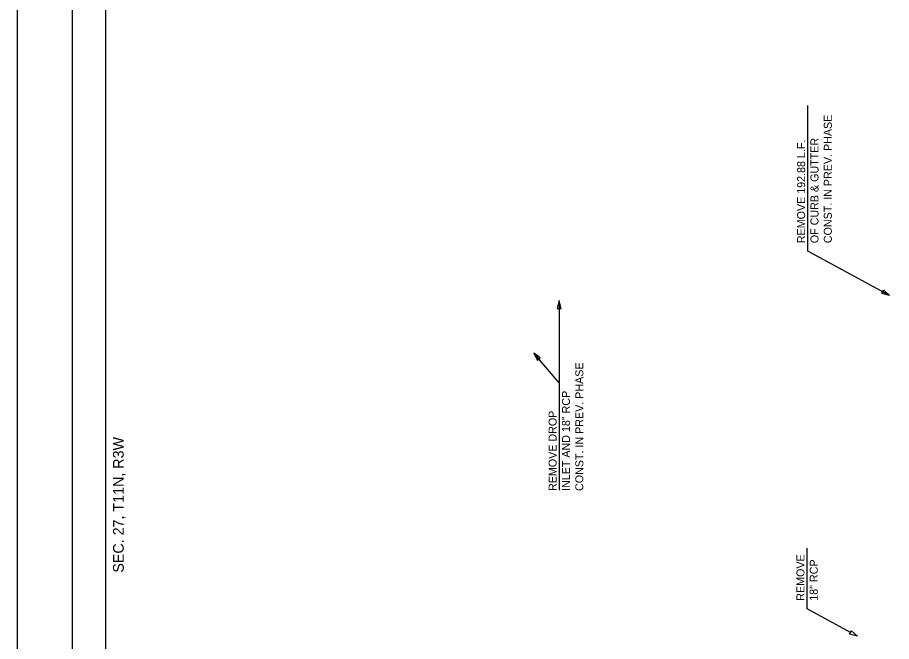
# Model space of a CAD drawing. Extents: x 2150259 to 2151459, y 143090 to 145092.
# Drawn here: x 2150259 to 2150914, y 144157 to 144624 of the extents above; entities that cross this region are included whole.
import ezdxf

# ---------------------------------------------------------------- set-up
doc = ezdxf.new("R2010")
doc.units = 0
for name, color, linetype in [('PR_Removal_Txt', 7, 'Continuous'), ('SHT_Plot_Shape_Full', 7, 'Continuous'), ('SHT_Plot_Shape_Half', 7, 'Continuous'), ('SHT_Sheet_Border', 7, 'Continuous'), ('SHT_Sheet_Txt', 7, 'Continuous')]:
    doc.layers.add(name, color=color, linetype=linetype)

msp = doc.modelspace()

# ---------------------------------------------------------------- linework, layer by layer
at = {"layer": 'PR_Removal_Txt'}
for p, q in [((2150851.5, 144455.26), (2150851.5, 144558.45)), ((2150665.27, 144350.64), (2150646.15, 144372.91)), ((2150665.27, 144344.64), (2150665.27, 144270.07)), ((2150850.96, 144187.3), (2150850.96, 144226.71))]:
    msp.add_line(p, q, dxfattribs=at)
for points in [[(2150912.82, 144416.01), (2150851.5, 144449.26), (2150851.5, 144455.26)], [(2150665.12, 144412.22), (2150665.27, 144350.64), (2150665.27, 144344.64)], [(2150883.51, 144163.57), (2150850.96, 144181.3), (2150850.96, 144187.3)]]:
    msp.add_lwpolyline(points, dxfattribs=at)
for points in [[(2150912.82, 144416.01), (2150907.01, 144417.5), (2150908.39, 144420.06)], [(2150665.12, 144412.22), (2150663.68, 144406.39), (2150666.59, 144406.4)], [(2150646.15, 144372.91), (2150648.83, 144367.55), (2150651.04, 144369.44)], [(2150888.63, 144160.79), (2150882.82, 144162.29), (2150884.21, 144164.85)]]:
    msp.add_lwpolyline(points, close=True, dxfattribs=at)
at = {"layer": 'SHT_Plot_Shape_Full'}
msp.add_lwpolyline([(2150259.22, 143292.05), (2150259.22, 145092.05), (2151459.22, 145092.05), (2151459.22, 143292.05)], close=True, dxfattribs=at)
at = {"layer": 'SHT_Plot_Shape_Half'}
msp.add_lwpolyline([(2150300.47, 143373.92), (2150300.47, 145073.92), (2151400.47, 145073.92), (2151400.47, 143373.92)], close=True, dxfattribs=at)
at = {"layer": 'SHT_Sheet_Border'}
msp.add_lwpolyline([(2151375.47, 145046.42), (2151375.47, 143471.42), (2150325.47, 143471.42), (2150325.47, 145046.42)], close=True, dxfattribs=at)

# ---------------------------------------------------------------- texts
at = {"layer": 'PR_Removal_Txt'}
for s, p in [('CONST. IN PREV. PHASE', (2150869.5, 144455.26)), ('REMOVE 192.88 L.F.', (2150849.5, 144455.26)), ('OF CURB & GUTTER', (2150859.5, 144455.26)), ('CONST. IN PREV. PHASE', (2150683.27, 144269.57)), ('INLET AND 18" RCP', (2150673.27, 144269.57)), ('REMOVE DROP', (2150663.27, 144269.57)), ('REMOVE', (2150848.96, 144187.3)), ('18" RCP', (2150858.96, 144187.3))]:
    msp.add_text(s, height=6, rotation=90, dxfattribs=at).set_placement(p)
at = {"layer": 'SHT_Sheet_Txt'}
msp.add_text('SEC. 27, T11N, R3W', height=8, rotation=90.02698, dxfattribs=at).set_placement((2150338.87, 144208.35))

doc.saveas('drawing.dxf')
